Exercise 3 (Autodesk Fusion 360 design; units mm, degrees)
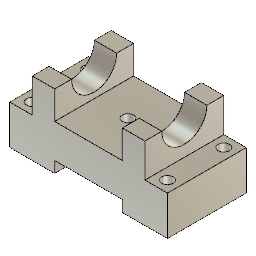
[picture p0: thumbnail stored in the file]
sketch "Sketch1" plane through (0, 0, 0) normal (0, 1, 0) x axis (1, 0, 0)
  line L1 (-70, 17.5) -> (-70, -17.5)
  line L2 (70, -17.5) -> (70, 17.5)
  line L3 (-70, 17.5) -> (70, -17.5)
  line L4 (70, 17.5) -> (-70, -17.5)
  line L5 (-30, 7.5) -> (-30, 17.5)
  line L6 (30, 7.5) -> (-30, 7.5)
  line L7 (30, 17.5) -> (30, 7.5)
  line L8 (0, -35.0095) -> (0, 0)
  line L9 (-30, 17.5) -> (-70, 17.5)
  line L10 (70, 17.5) -> (30, 17.5)
  line L11 (-50, -47.5) -> (-50, -17.5)
  line L12 (-30, -47.5) -> (-50, -47.5)
  line L13 (-30, -22.5) -> (-30, -47.5)
  line L14 (50, -47.5) -> (50, -17.5)
  line L15 (30, -47.5) -> (50, -47.5)
  line L16 (30, -22.5) -> (30, -47.5)
  line L17 (-70, -17.5) -> (-50, -17.5)
  line L18 (50, -17.5) -> (70, -17.5)
  line L19 (30, -22.5) -> (-30, -22.5)
  point P6 (0, 0)
  point P1 (0, 0)
  point P10 (30, 17.5)
  point P11 (0, 0)
  point P13 (-50, -17.5)
  point P4 (-70, 17.5)
  point P5 (70, 17.5)
  point P3 (-70, -17.5)
  point P9 (30, 7.5)
  point P17 (50, -47.5)
  point P18 (30, -47.5)
  horizontal L18
  perpendicular L1 L18
  parallel L9 L18
  parallel L1 L2
  coincident L3 P6
  coincident L4 P6
  coincident P1 P6
  perpendicular L5 L9
  perpendicular L5 L6
  coincident P10 L9
  perpendicular L7 L9
  coincident P1 P11
  perpendicular L8 L18
  collinear L9 L10
  symmetric L5 L7 L8
  coincident P13 L18
  perpendicular L11 L18
  perpendicular L11 L12
  perpendicular L13 L18
  perpendicular L14 L18
  perpendicular L11 L15
  perpendicular L16 L18
  collinear L17 L18
  symmetric L8 L13 L16
  equal L12 L15
  perpendicular L16 L19
  equal L13 L16
  dimension "d1" distance P4 P5 = 140
  dimension "d2" distance P3 P4 = 35
  dimension "d3" distance P9 P10 = 10
  dimension "d4" distance P17 P18 = 20
  dimension "d5" distance L17 L19 = 5
  dimension "d6" distance L13 L16 = 60
  dimension "d7" distance L10 L15 = 65
  dimension "d8" distance L5 L7 = 60
extrude "Extrude1" new body sketch "Sketch1" profile of L18 L1 L10 L2 L5 L6 L7 L11 L12 L13 L14 L15 L16 L19 distance 70
sketch "Sketch2" plane through (50, 0, 0) normal (1, 0, 0) x axis (0, 1, 0)
  line L1 (35, 17.5) -> (-35, 17.5)
  line L2 (35, 47.5) -> (35, 17.5)
  line L3 (-35, 47.5) -> (35, 47.5)
  line L4 (-35, 17.5) -> (-35, 47.5)
  circle C1 centre (0, 47.5) radius 20
  point P6 (0, 47.5)
  midpoint L3 P6
  dimension "d11" diameter C1 = 40
extrude "Extrude2" cut sketch "Sketch2" profile of L3 C1 no distance stored
sketch "Sketch3" plane through (0, 0, 22.5) normal (0, 0, 1) x axis (-1, 0, 0)
  line L1 (-30, -35) -> (-30, 35)
  line L2 (30, -35) -> (-30, -35)
  line L3 (30, 35) -> (30, -35)
  line L4 (-30, 35) -> (30, 35)
  circle C1 centre (0, 0) radius 5
  point P1 (0, 0)
  point P6 (0, 0)
  coincident P1 P6
  dimension "d13" diameter C1 = 10
extrude "Extrude3" cut sketch "Sketch3" profile of C1 no distance stored
sketch "Sketch4" plane through (0, 0, 17.5) normal (0, 0, 1) x axis (-1, 0, 0)
  line L1 (-70, -35) -> (-70, 35)
  line L2 (-50, -35) -> (-70, -35)
  line L3 (-50, 35) -> (-50, -35)
  line L4 (-70, 35) -> (-50, 35)
  circle C1 centre (-60, -25) radius 5
  circle C2 centre (-60, 25) radius 5
  point P6 (-60, -25)
  point P7 (-60, 25)
  equal C1 C2
  vertical P6 P7
  dimension "d15" diameter C1 = 10
  dimension "d16" distance L1 P6 = 10
  dimension "d17" distance L2 P6 = 10
  dimension "d18" distance L4 P7 = 10
extrude "Extrude4" cut sketch "Sketch4" profile of C1 C2 no distance stored
mirror "Mirror1"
